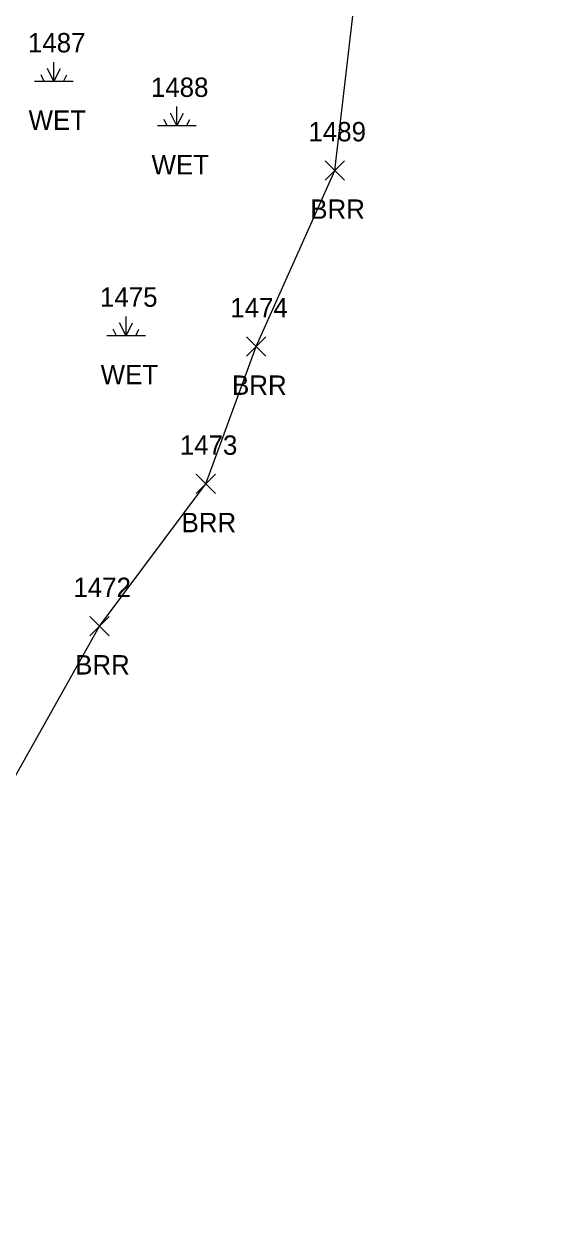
# Model space of a CAD drawing. Extents: x 1554917 to 1555870, y 813367 to 816333.
# Drawn here: x 1555281.5 to 1555336, y 813931.9 to 814056.2 of the extents above; entities that cross this region are included whole.
import ezdxf

# ---------------------------------------------------------------- set-up
doc = ezdxf.new("R2010")
doc.units = 0
for name, color, linetype in [('L_A', 7, 'Continuous'), ('L_I', 7, 'Continuous'), ('L_TIC', 7, 'Continuous'), ('LABL', 7, 'Continuous'), ('LWET', 7, 'Continuous')]:
    doc.layers.add(name, color=color, linetype=linetype)

msp = doc.modelspace()

# ---------------------------------------------------------------- linework, layer by layer
at = {"layer": 'L_TIC'}
for points in [[(1555312.64, 814040.1), (1555314.64, 814042.1)], [(1555314.64, 814040.1), (1555312.64, 814042.1)], [(1555304.54, 814021.92), (1555306.54, 814023.92)], [(1555306.54, 814021.92), (1555304.54, 814023.92)], [(1555299.33, 814007.73), (1555301.33, 814009.73)], [(1555301.33, 814007.73), (1555299.33, 814009.73)], [(1555288.33, 813993.04), (1555290.33, 813995.04)], [(1555290.33, 813993.04), (1555288.33, 813995.04)]]:
    msp.add_lwpolyline(points, dxfattribs=at)
at = {"layer": 'LABL'}
msp.add_lwpolyline([(1555246.98, 813903.97), (1555255.51, 813921.27), (1555270.42, 813951.6), (1555277.93, 813973.79), (1555289.33, 813994.04), (1555300.33, 814008.73), (1555305.54, 814022.92), (1555313.64, 814041.1), (1555318.32, 814081.03), (1555326.1, 814100.25), (1555336, 814125.43)], dxfattribs=at)
at = {"layer": 'LWET'}
for p, q in [((1555284.62, 814050.29), (1555284.62, 814052.29)), ((1555283.62, 814050.29), (1555283.29, 814050.96)), ((1555284.62, 814050.29), (1555283.95, 814051.63)), ((1555284.62, 814050.29), (1555285.29, 814051.63)), ((1555285.62, 814050.29), (1555285.95, 814050.96)), ((1555286.62, 814050.29), (1555282.62, 814050.29)), ((1555297.33, 814045.69), (1555296.67, 814047.02)), ((1555297.33, 814045.69), (1555297.33, 814047.69)), ((1555297.33, 814045.69), (1555298, 814047.02)), ((1555299.33, 814045.69), (1555295.33, 814045.69)), ((1555296.33, 814045.69), (1555296, 814046.35)), ((1555298.33, 814045.69), (1555298.67, 814046.35)), ((1555292.08, 814024.02), (1555292.08, 814026.02)), ((1555291.08, 814024.02), (1555290.74, 814024.69)), ((1555292.08, 814024.02), (1555291.41, 814025.35)), ((1555292.08, 814024.02), (1555292.74, 814025.35)), ((1555293.08, 814024.02), (1555293.41, 814024.69)), ((1555294.08, 814024.02), (1555290.08, 814024.02))]:
    msp.add_line(p, q, dxfattribs=at)

# ---------------------------------------------------------------- texts
at = {"layer": 'L_A'}
for s, p in [('WET', (1555282, 814045.29)), ('WET', (1555294.71, 814040.69)), ('BRR', (1555311.12, 814036.1)), ('WET', (1555289.45, 814019.02)), ('BRR', (1555303.03, 814017.92)), ('BRR', (1555297.81, 814003.73)), ('BRR', (1555286.81, 813989.04))]:
    msp.add_text(s, height=2, dxfattribs=at).set_placement(p)
at = {"layer": 'L_I'}
for s, p in [('1487', (1555281.93, 814053.29)), ('1488', (1555294.64, 814048.69)), ('1489', (1555310.93, 814044.1)), ('1475', (1555289.38, 814027.02)), ('1474', (1555302.85, 814025.92)), ('1473', (1555297.63, 814011.73)), ('1472', (1555286.63, 813997.04))]:
    msp.add_text(s, height=2, dxfattribs=at).set_placement(p)

doc.saveas('drawing.dxf')
